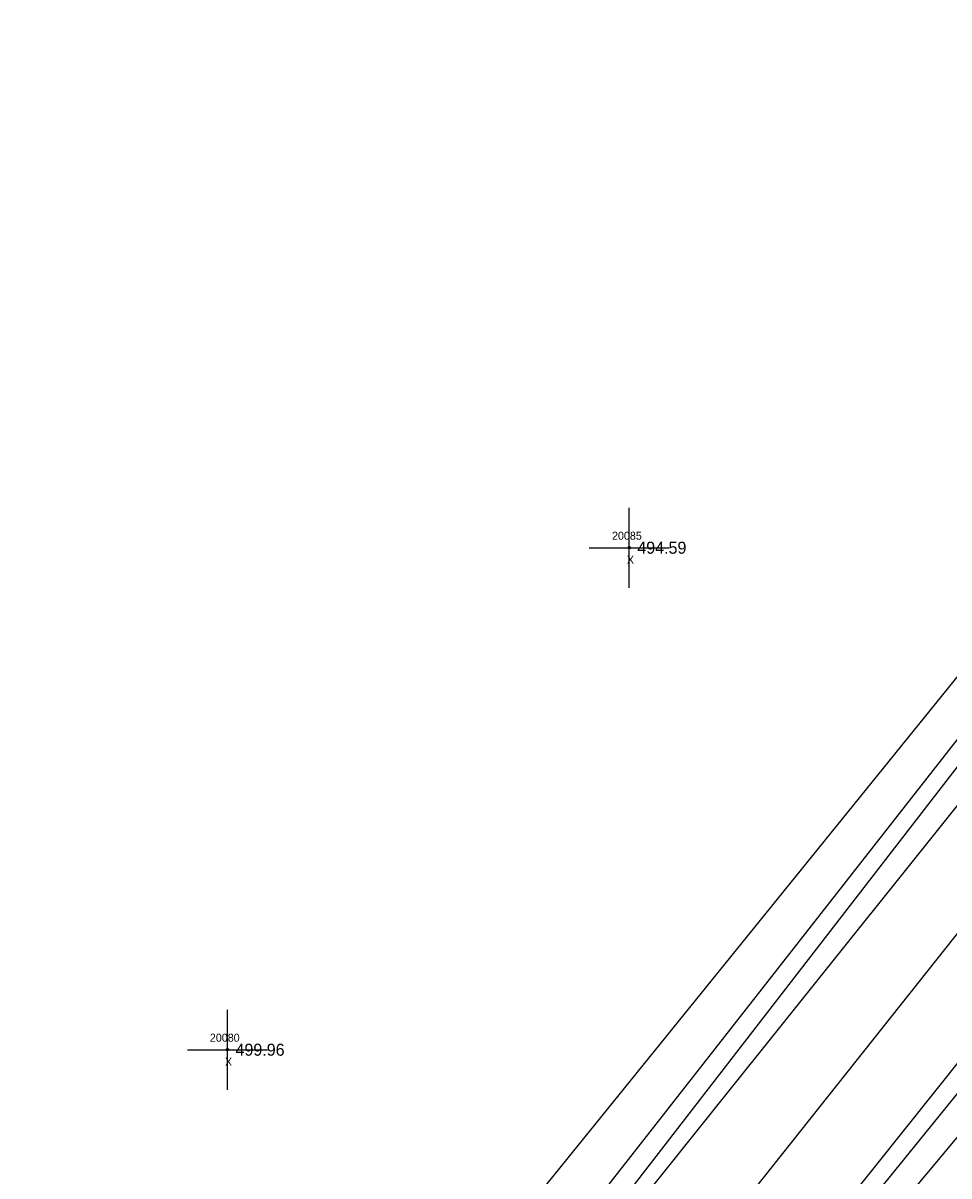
# Model space of a CAD drawing. Extents: x 1789565 to 1790548, y 909019 to 910194.
# Drawn here: x 1789609.4 to 1789725, y 909163.2 to 909307.2 of the extents above; entities that cross this region are included whole.
import ezdxf

# ---------------------------------------------------------------- set-up
doc = ezdxf.new("R2010")
doc.units = 0
for name, color, linetype in [('RD_DTM_BkLn1', 7, 'Continuous'), ('RD_DTM_BkLn2', 7, 'Continuous'), ('RD_EX_H2O', 7, 'Continuous'), ('RD_EX_Misc', 7, 'Continuous'), ('RD_EX_Misc_txCode', 7, 'Continuous'), ('RD_EX_Road', 7, 'Continuous'), ('RD_EX_TX_Misc_ELEV', 7, 'Continuous'), ('RD_SMD_Locator', 7, 'Continuous')]:
    doc.layers.add(name, color=color, linetype=linetype)

msp = doc.modelspace()

# ---------------------------------------------------------------- linework, layer by layer
at = {"layer": 'RD_DTM_BkLn1'}
msp.add_lwpolyline([(1789624.5, 909066.24), (1789686.15, 909143.09), (1789745.11, 909217.37), (1789803.6, 909290.4), (1789864.63, 909366.97), (1789927.82, 909445.41), (1789987.57, 909520.69), (1790044.94, 909592.68)], dxfattribs=at)
at = {"layer": 'RD_DTM_BkLn2'}
for points in [[(1789614.08, 909073.14), (1789676.68, 909150.35), (1789735.2, 909226.02), (1789793.81, 909297.32), (1789853.39, 909374.42), (1789917.15, 909454.46), (1789977.25, 909529.33), (1790025.37, 909589.9), (1790030.46, 909600.52), (1790034.43, 909600.71)], [(1789609.37, 909078.57), (1789669.9, 909156.07), (1789730.1, 909230.49), (1789787.39, 909303.09), (1789833.49, 909359.71), (1789838.38, 909362.25)], [(1789633.72, 909058.98), (1789695.06, 909135.14), (1789755.1, 909209.21), (1789813.73, 909282.9), (1789852.08, 909326.88), (1789859.67, 909329.95), (1789891.2, 909324.8)]]:
    msp.add_lwpolyline(points, dxfattribs=at)
at = {"layer": 'RD_EX_H2O'}
for points in [[(1789612.38, 909074.81), (1789674.47, 909151.77), (1789733.61, 909227.27), (1789792.01, 909298.88), (1789838.38, 909362.25)], [(1789635.36, 909056.96), (1789697.2, 909133.38), (1789758.1, 909206.33), (1789818.22, 909280.06), (1789854.18, 909324.3), (1789860.54, 909326.82), (1789889.88, 909320.33)]]:
    msp.add_lwpolyline(points, dxfattribs=at)
at = {"layer": 'RD_EX_Misc'}
for p, q in [((1789685.11, 909236.67), (1789685.11, 909246.67)), ((1789680.11, 909241.67), (1789690.11, 909241.67)), ((1789634.91, 909173.94), (1789634.91, 909183.94)), ((1789629.91, 909178.94), (1789639.91, 909178.94))]:
    msp.add_line(p, q, dxfattribs=at)
at = {"layer": 'RD_EX_Road'}
for points in [[(1789616.04, 909073.03), (1789678, 909149.36), (1789737.65, 909223.89), (1789795.32, 909296.33), (1789856.01, 909372.29), (1789919.82, 909451.94), (1789979.86, 909527.13), (1790037.32, 909598.58), (1790044.94, 909592.68)], [(1789632.25, 909060.17), (1789693.63, 909136.51), (1789752.94, 909210.84), (1789811.79, 909284.47), (1789846.6, 909328.43), (1789872.88, 909361.39), (1789936.05, 909439.58), (1789995.85, 909514.58), (1790052.72, 909586.51), (1790044.94, 909592.68)]]:
    msp.add_lwpolyline(points, dxfattribs=at)
at = {"layer": 'RD_SMD_Locator'}
for centre in [(1789685.11, 909241.67), (1789634.91, 909178.94)]:
    msp.add_circle(centre, 0.15, dxfattribs=at)

# ---------------------------------------------------------------- texts
at = {"layer": 'RD_EX_Misc_txCode'}
for s, p in [('20085', (1789682.95, 909242.67)), ('X', (1789684.8, 909239.67)), ('20080', (1789632.71, 909179.94)), ('X', (1789634.59, 909176.94))]:
    msp.add_text(s, height=1, dxfattribs=at).set_placement(p)
at = {"layer": 'RD_EX_TX_Misc_ELEV'}
for s, p in [('494.59', (1789686.11, 909240.92)), ('499.96', (1789635.91, 909178.19))]:
    msp.add_text(s, height=1.5, dxfattribs=at).set_placement(p)

doc.saveas('drawing.dxf')
